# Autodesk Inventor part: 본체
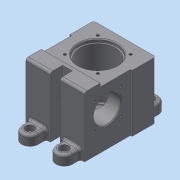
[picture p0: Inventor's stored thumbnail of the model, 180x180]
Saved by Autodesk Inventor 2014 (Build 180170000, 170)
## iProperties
Created: 2024-11
Part Number: 본체
Material: 일반
Document SubType Name: Modeling
Designer: dg
Density: 1 g/cm^3
Appearance: 기본값
Author: dg
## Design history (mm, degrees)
sketch "스케치1"
  geometry: L1 (-38, 42.5)-(38, 42.5); L2 (38, 42.5)-(38, -42.5); L3 (38, -42.5)-(-38, -42.5); L4 (-38, -42.5)-(-38, 42.5); 3 further points
  constraints: 8 end point, 2 midpoint, 2 parallel, 1 horizontal, 1 horizontal alignment, 1 perpendicular, 1 vertical alignment
  dimensions: "d0" = 85 distance of L3.end L1.start; "d1" = 76 distance of L1.start L1.end
extrude "돌출1" new body sketch "스케치1" distance "d2" = 74; taper "d3" = 0 deg
sketch "스케치3"
  geometry: L1 (0, 74)-(0, 0) reference; L2 (76, 0)-(0, 0); L3 (0, 0)-(0, 4); L4 (0, 4)-(76, 4); L5 (76, 4)-(76, 0); 1 further point
  constraints: 8 end point, 2 parallel, 1 horizontal, 1 perpendicular, 1 point on line
  dimensions: "d9" = 4 distance between parallel lines of L4 L2
extrude "돌출3" cut sketch "스케치3" distance "d10" = 66; taper "d11" = 0 deg
sketch "스케치4"
  geometry: L1 (-23.5, 70)-(42.5, 70) reference; L2 (42.5, 70)-(42.5, 0) reference; L3 (42.5, 0)-(-42.5, 0) reference; L4 (-42.5, 0)-(-42.5, 74) reference; L5 (-42.5, 74)-(-23.5, 74) reference; L6 (-23.5, 74)-(-23.5, 70) reference; L7 (0, 70)-(23.5, 70); L8 (17.5, 4.172)-(15, 4.172); L9 (15, 4.172)-(15, 2.472); 1 further point
  constraints: 6 end point, 2 point on line, 1 perpendicular
  node "절단 모서리 투영1"
sketch "스케치9"
  geometry: L1 (76, -74)-(0, -74) reference; L2 (0, 0)-(2, 0); L3 (2, 0)-(2, -74); L4 (2, -74)-(0, -74); L5 (0, -74)-(0, 0); 2 further points
  constraints: 8 end point, 2 parallel, 1 horizontal, 1 perpendicular, 1 point on line
  dimensions: "d30" = 2 distance of L2.start L2.end
extrude "돌출8" cut sketch "스케치9" distance "d31" = 56; taper "d32" = 0 deg
sketch "스케치10"
  geometry: L1 (38, 42.5)-(-38, 42.5) reference; L2 (-31, 52.5)-(-31, 42.5); L3 (-11, 52.5)-(-11, 42.5); A1 r 10 centre (-21, 52.5) between (-11, 52.5) and (-31, 52.5); 1 further point
  constraints: 4 end point, 2 perpendicular, 2 point on circle, 2 point on line, 2 tangent, 1 centre point
  dimensions: "d36" = 20 diameter of A1; "d37" = 21 horizontal distance of point (0, 0) A1.centre; "d38" = 10 distance from line of L1 A1.centre
extrude "돌출9" join sketch "스케치10" distance "d39" = 12; taper "d40" = 0 deg
hole "구멍1" diameter "d43" = 6.6; stored, may be unused: countersink angle "d47" = 90 deg, drill point angle "d49" = 118 deg; dims "d41" = 10, "d42" = 10, "d44" = 6, "d45" = 11, "d46" = 6.6, "d48" = 8
sketch "스케치12"
  geometry: L1 (42.5, 70)-(42.5, 0) reference; L2 (42.5, 0)-(-42.5, 0) reference; L3 (-42.5, 0)-(-42.5, 74) reference; L4 (-42.5, 74)-(-23.5, 74) reference; L5 (-23.5, 74)-(-23.5, 70) reference; L6 (-23.5, 70)-(42.5, 70) reference; L7 (9.5, 70)-(9.5, 0); L8 (33, 70)-(33, 66); L9 (33, 66)-(31.5, 66); L10 (31.5, 66)-(31.5, 21); L11 (28.5, 18)-(27, 18); L12 (27, 18)-(27, 7.6); L13 (26.4, 7)-(24.5, 7); L14 (24.5, 7)-(24.5, 7); L15 (21.5, 4)-(9.5, 4); A1 r 3 centre (28.5, 21) between (28.5, 18) and (31.5, 21); A2 r 0.6 centre (26.4, 7.6) between (26.4, 7) and (27, 7.6); A3 r 3 centre (21.5, 7) between (21.5, 4) and (24.5, 7); 3 further points
  constraints: 18 end point, 7 point on line, 6 point on circle, 6 tangent, 5 perpendicular, 3 centre point, 3 parallel, 1 equal radius, 1 midpoint, 1 vertical
  dimensions: "d55" = 33 distance between parallel lines of L7 L1; "d56" = 47 diameter of L8 L7; "d57" = 44 diameter of L10 L7; "d58" = 35 diameter of L12 L7; "d59" = 30 diameter of L14 L7; "d60" = 4 distance of L8.start L8.end; "d61" = 56 distance between parallel lines of L11 L4; "d62" = 11 distance of L11.end point (27, 7); "d63" = 3 distance of L13.end point (24.5, 4); "d64" = 3 radius of A1; "d65" = 0.6 radius of A2
revolve "회전1" sketch "스케치12" stored, may be unused: angle "d66" = 90 deg
sketch "스케치13"
  geometry: L1 (0, -10)-(0, 0) reference; L2 (0, 85)-(70, 85) reference; C1 r 16.5 at (42, 28); 1 further point
  constraints: 1 centre point
  dimensions: "d67" = 42 distance from line of C1.centre L1; "d68" = 33 diameter of C1; "d69" = 57 distance from line of C1.centre L2
extrude "돌출11" cut sketch "스케치13" stored distance "d70" = 12; taper "d71" = 0 deg
sketch "스케치14" dims "d72" = 57
  geometry: L1 (38, -33)-(52.157, -33); L2 (58.153, -12.847)-(38, -33); C1 r 23.5 at (38, -33) reference; 1 further point
  constraints: 4 end point, 1 coincident, 1 horizontal, 3 other
  dimensions: "d73" = 45 deg angle of L1 L2
hole "구멍2" sketch "스케치14" at (58.153, -12.847) diameter "d74" = 3.242; stored, may be unused: countersink angle "d78" = 90 deg, drill point angle "d80" = 118 deg; dims "d75" = 8, "d76" = 11, "d77" = 6.6, "d79" = 10
sketch "스케치15"
  geometry: C1 r 16.5 at (42, 28) reference; 5 further points
  constraints: 2 horizontal alignment, 2 vertical alignment
  dimensions: "d84" = 32 distance of point (26, 12) point (26, 44); "d85" = 16 horizontal distance of point (26, 12) C1.centre; "d86" = 32 distance of point (58, 12) point (26, 12); "d87" = 16 horizontal distance of point (58, 12) C1.centre
hole "구멍3" sketch "스케치15" at (26, 44), (26, 12), (58, 44), (58, 12) diameter "d88" = 3.242; stored, may be unused: countersink angle "d92" = 90 deg, drill point angle "d94" = 118 deg; dims "d89" = 8, "d90" = 11, "d91" = 6.6, "d93" = 10
fillet "모깎기1" dims "d95" = 3
sketch "스케치16"
  geometry: L1 (-36, -42.5)-(36, -42.5) reference; L2 (-6, -42.5)-(6, -42.5); L3 (6, -42.5)-(6, -27.5); L4 (6, -27.5)-(-6, -27.5); L5 (-6, -27.5)-(-6, -42.5); 3 further points
  constraints: 8 end point, 2 midpoint, 2 parallel, 1 coincident, 1 horizontal, 1 perpendicular, 1 vertical alignment
  dimensions: "d96" = 12 distance of L3.end L4.end; "d97" = 15 distance between parallel lines of L4 L1
extrude "돌출12" cut sketch "스케치16" stored distance "d98" = 12; taper "d99" = 0 deg
fillet "모깎기2" dims "d100" = 3
fillet "모깎기3" dims "d101" = 3
fillet "모깎기4" dims "d102" = 3
chamfer "모따기1" distance "d103" = 1; stored, may be unused: second distance "d104" = 2, angle "d105" = 45 deg
sketch "스케치17"
  geometry: L1 (27, 70)-(43, 70) reference; L2 (0, 0)-(70, 0) reference; 3 further points
  constraints: 1 midpoint, 1 vertical alignment, 1 other
  dimensions: "d106" = 20 distance from line of point (35, 20) L2
feature "엠보싱1" sketch "스케치17" dims "d0" = 85, "d1" = 76, "d107" = 0.5, "d108" = 0
sketch "스케치18"
  geometry: L1 (0, 0)-(12, 0) reference; L2 (12, -74)-(0, -74) reference; 5 further points
  constraints: 2 midpoint, 2 vertical alignment
  dimensions: "d109" = 12 distance from line of L1 point (6, -12); "d110" = 40 distance of point (6, -12) point (6, -52)
hole "구멍4" sketch "스케치18" at (6, -12), (6, -52) diameter "d111" = 3.242; stored, may be unused: countersink angle "d115" = 90 deg, drill point angle "d117" = 118 deg; dims "d112" = 8, "d113" = 11, "d114" = 6.6, "d116" = 10
node "솔리드1"
mirror "대칭1"
mirror "대칭2"
mirror "대칭3"
pattern_circular "원형 패턴1" dims angle "d82" = 360 deg
mirror "대칭4"
node "절단 모서리 투영4"
